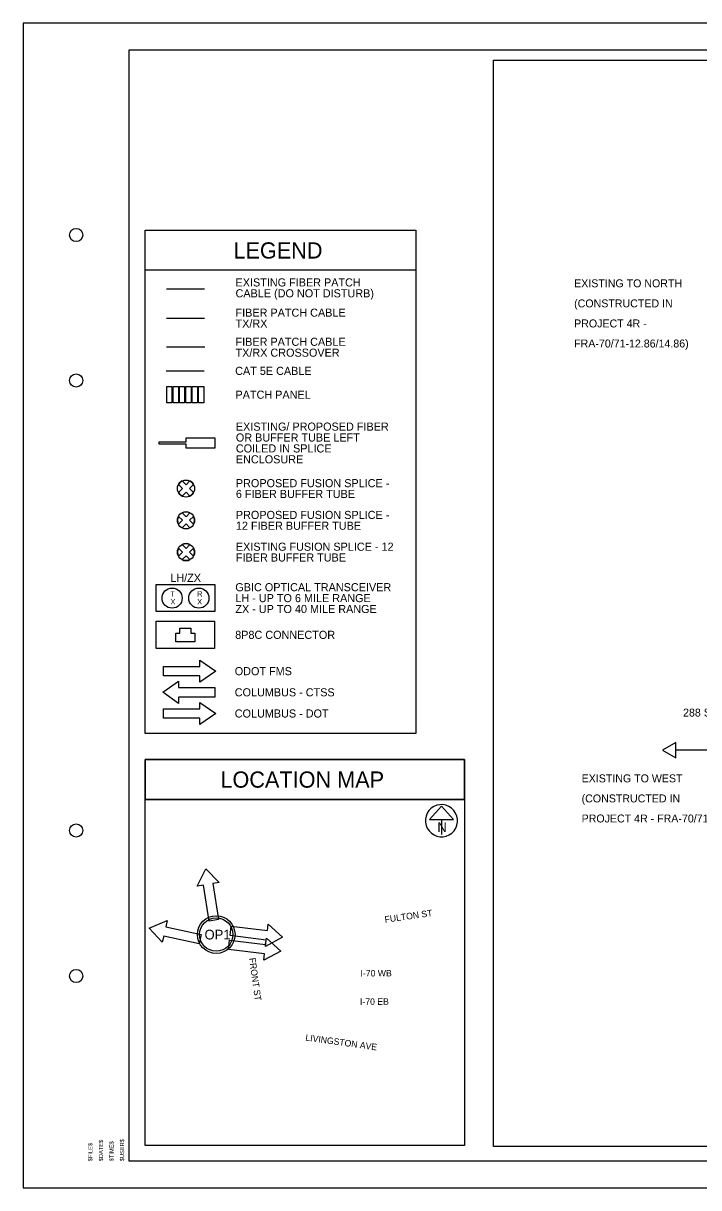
# Model space of a CAD drawing. Extents: x 1805893 to 1833564, y 708898 to 716199.
# Drawn here: x 1831322.5 to 1831577.6, y 715759.4 to 716199.4 of the extents above; entities that cross this region are included whole.
import ezdxf

# ---------------------------------------------------------------- set-up
doc = ezdxf.new("R2010")
doc.units = 0
for name, color, linetype in [('BR_P_Sub_Hidden', 7, 'Continuous'), ('BR_X_Slab_Object', 7, 'Continuous'), ('SH_Border', 7, 'Continuous'), ('SH_Cut_Line', 7, 'Continuous'), ('SH_Data', 7, 'Continuous'), ('SH_Text', 7, 'Continuous'), ('UT_X_Misc_Cells', 7, 'Continuous')]:
    doc.layers.add(name, color=color, linetype=linetype)

msp = doc.modelspace()

# ---------------------------------------------------------------- linework, layer by layer
at = {"layer": 'BR_P_Sub_Hidden'}
msp.add_lwpolyline([(1831500.15, 716185.43), (1831958.68, 716185.43), (1831958.68, 715774.93), (1831500.15, 715774.93)], close=True, dxfattribs=at)
at = {"layer": 'SH_Border'}
msp.add_lwpolyline([(1831362.49, 716189.4), (1831992.49, 716189.4), (1831992.49, 715769.4), (1831362.49, 715769.4)], close=True, dxfattribs=at)
for centre in [(1831342.49, 716119.4), (1831342.49, 716064.4), (1831342.49, 715894.4), (1831342.49, 715839.4)]:
    msp.add_circle(centre, 2.5, dxfattribs=at)
at = {"layer": 'SH_Cut_Line'}
msp.add_lwpolyline([(1831322.49, 715759.4), (1832002.49, 715759.4), (1832002.49, 716199.4), (1831322.49, 716199.4)], close=True, dxfattribs=at)
at = {"layer": 'SH_Data'}
for p, q in [((1831376.65, 716099), (1831390.99, 716099)), ((1831376.65, 716088), (1831390.99, 716088)), ((1831383.96, 716024.96), (1831382.46, 716026.45)), ((1831383.96, 716024.96), (1831382.46, 716026.45)), ((1831383.96, 716024.96), (1831385.45, 716026.45)), ((1831385.45, 716026.45), (1831383.96, 716024.96)), ((1831382.6, 716023.6), (1831381.11, 716025.09)), ((1831381.11, 716025.09), (1831382.6, 716023.6)), ((1831381.11, 716022.11), (1831382.6, 716023.6)), ((1831382.6, 716023.6), (1831381.11, 716022.11)), ((1831382.46, 716020.75), (1831383.96, 716022.25)), ((1831382.46, 716020.75), (1831383.96, 716022.25)), ((1831385.45, 716020.75), (1831383.96, 716022.25)), ((1831383.96, 716022.25), (1831385.45, 716020.75)), ((1831385.31, 716023.6), (1831386.8, 716025.09)), ((1831385.31, 716023.6), (1831386.8, 716025.09)), ((1831386.8, 716022.11), (1831385.31, 716023.6)), ((1831386.8, 716022.11), (1831385.31, 716023.6)), ((1831382.6, 716011.59), (1831381.11, 716013.08)), ((1831382.6, 716011.59), (1831381.11, 716013.08)), ((1831383.96, 716012.95), (1831382.46, 716014.44)), ((1831382.46, 716014.44), (1831383.96, 716012.95)), ((1831383.96, 716012.95), (1831385.45, 716014.44)), ((1831383.96, 716012.95), (1831385.45, 716014.44)), ((1831385.31, 716011.59), (1831386.8, 716013.08)), ((1831386.8, 716013.08), (1831385.31, 716011.59)), ((1831381.11, 716010.1), (1831382.6, 716011.59)), ((1831381.11, 716010.1), (1831382.6, 716011.59)), ((1831382.46, 716008.74), (1831383.96, 716010.24)), ((1831383.96, 716010.24), (1831382.46, 716008.74)), ((1831385.45, 716008.74), (1831383.96, 716010.24)), ((1831385.45, 716008.74), (1831383.96, 716010.24)), ((1831386.8, 716010.1), (1831385.31, 716011.59)), ((1831385.31, 716011.59), (1831386.8, 716010.1)), ((1831382.6, 715999.59), (1831381.11, 716001.08)), ((1831382.6, 715999.59), (1831381.11, 716001.08)), ((1831381.11, 715998.1), (1831382.6, 715999.59)), ((1831381.11, 715998.1), (1831382.6, 715999.59)), ((1831383.96, 716000.95), (1831382.46, 716002.44)), ((1831382.46, 716002.44), (1831383.96, 716000.95)), ((1831383.96, 716000.95), (1831385.45, 716002.44)), ((1831383.96, 716000.95), (1831385.45, 716002.44)), ((1831385.31, 715999.59), (1831386.8, 716001.08)), ((1831386.8, 716001.08), (1831385.31, 715999.59)), ((1831386.8, 715998.1), (1831385.31, 715999.59)), ((1831385.31, 715999.59), (1831386.8, 715998.1)), ((1831382.46, 715996.74), (1831383.96, 715998.23)), ((1831383.96, 715998.23), (1831382.46, 715996.74)), ((1831385.45, 715996.74), (1831383.96, 715998.23)), ((1831385.45, 715996.74), (1831383.96, 715998.23)), ((1831375.5, 715956.4), (1831389.23, 715956.4)), ((1831375.5, 715952.8), (1831375.5, 715956.4)), ((1831389.23, 715956.4), (1831389.23, 715958.8)), ((1831389.23, 715952.8), (1831375.5, 715952.8)), ((1831381.16, 715950.8), (1831381.16, 715948.4)), ((1831389.23, 715950.4), (1831389.23, 715952.8)), ((1831381.16, 715948.4), (1831394.9, 715948.4)), ((1831394.9, 715948.4), (1831394.9, 715944.8)), ((1831394.9, 715944.8), (1831381.16, 715944.8)), ((1831381.16, 715944.8), (1831381.16, 715942.4)), ((1831389.23, 715940.4), (1831389.23, 715942.8)), ((1831375.5, 715940.4), (1831389.23, 715940.4)), ((1831375.5, 715936.8), (1831375.5, 715940.4)), ((1831389.23, 715936.8), (1831375.5, 715936.8)), ((1831389.23, 715934.4), (1831389.23, 715936.8)), ((1831568.97, 715927.63), (1831563.95, 715924.73)), ((1831563.95, 715924.73), (1831568.97, 715921.83)), ((1831568.97, 715921.83), (1831568.97, 715927.63)), ((1831611.7, 715924.73), (1831568.97, 715924.73))]:
    msp.add_line(p, q, dxfattribs=at)
for points in [[(1831368.49, 716121.24), (1831470.72, 716121.24), (1831470.72, 716106.12), (1831368.49, 716106.12)], [(1831470.72, 716121.24), (1831470.72, 715931.07), (1831368.49, 715931.07), (1831368.49, 716121.24)], [(1831378.66, 716062.19), (1831378.66, 716055.94), (1831376.7, 716055.94), (1831376.7, 716062.19)], [(1831381.06, 716062.19), (1831381.06, 716055.94), (1831379.1, 716055.94), (1831379.1, 716062.19)], [(1831383.45, 716062.19), (1831383.45, 716055.94), (1831381.49, 716055.94), (1831381.49, 716062.19)], [(1831385.85, 716062.19), (1831385.85, 716055.94), (1831383.89, 716055.94), (1831383.89, 716062.19)], [(1831388.24, 716062.19), (1831388.24, 716055.94), (1831386.28, 716055.94), (1831386.28, 716062.19)], [(1831390.64, 716062.19), (1831390.64, 716055.94), (1831388.68, 716055.94), (1831388.68, 716062.19)], [(1831372.7, 715987.33), (1831394.8, 715987.33), (1831394.8, 715977.08), (1831372.7, 715977.08)], [(1831372.65, 715973.45), (1831394.74, 715973.45), (1831394.74, 715963.2), (1831372.65, 715963.2)], [(1831489.13, 715906.07), (1831368.49, 715906.07), (1831368.49, 715921.19), (1831489.13, 715921.19)], [(1831489.13, 715921.19), (1831368.49, 715921.19), (1831368.49, 715906.07), (1831489.13, 715906.07)], [(1831489.13, 715906.07), (1831368.49, 715906.07), (1831368.49, 715921.19), (1831489.13, 715921.19)], [(1831489.13, 715906.07), (1831489.13, 715775.4), (1831368.49, 715775.4), (1831368.49, 715906.07)], [(1831489.13, 715906.07), (1831489.13, 715775.4), (1831368.49, 715775.4), (1831368.49, 715906.07)]]:
    msp.add_lwpolyline(points, close=True, dxfattribs=at)
for points in [[(1831391.03, 716077), (1831376.65, 716077), (1831376.65, 716077), (1831376.65, 716077)], [(1831376.52, 716068.06), (1831390.86, 716068.09), (1831390.86, 716068.09)], [(1831373.66, 716041.13), (1831373.66, 716040.82), (1831373.66, 716040.51), (1831383.94, 716040.51), (1831383.94, 716038.98), (1831394.99, 716038.98), (1831394.99, 716042.66), (1831383.94, 716042.66), (1831383.94, 716041.13), (1831373.66, 716041.13)], [(1831394.99, 716038.98), (1831394.99, 716042.66), (1831383.94, 716042.66), (1831383.94, 716041.13), (1831373.66, 716041.13), (1831373.66, 716040.82), (1831373.66, 716040.51), (1831383.94, 716040.51), (1831383.94, 716038.98), (1831394.99, 716038.98)], [(1831385.82, 715968.93), (1831387.33, 715968.93), (1831387.33, 715965.7), (1831380.06, 715965.7), (1831380.06, 715968.93), (1831381.57, 715968.93)], [(1831381.57, 715968.93), (1831381.57, 715970.84), (1831385.82, 715970.84), (1831385.82, 715968.93)], [(1831389.23, 715958.8), (1831395.23, 715954.6), (1831389.23, 715950.4)], [(1831381.16, 715942.4), (1831375.16, 715946.6), (1831381.16, 715950.8)], [(1831389.23, 715942.8), (1831395.23, 715938.6), (1831389.23, 715934.4)]]:
    msp.add_lwpolyline(points, dxfattribs=at)
for centre, radius in [((1831383.96, 716023.6), 3.22), ((1831383.96, 716011.59), 3.22), ((1831383.96, 715999.59), 3.22), ((1831378.7, 715982.2), 3.81), ((1831388.8, 715982.2), 3.81)]:
    msp.add_circle(centre, radius, dxfattribs=at)
for centre, start, end in [((1831383.96, 716023.6), 117.647, 152.353), ((1831383.96, 716023.6), 27.647, 62.353), ((1831383.96, 716023.6), 207.647, 242.353), ((1831383.96, 716023.6), 297.647, 332.353), ((1831383.96, 716011.59), 152.353, 207.647), ((1831383.96, 716011.59), 62.353, 117.647), ((1831383.96, 716011.59), 332.353, 27.647), ((1831383.96, 716011.59), 242.353, 297.647), ((1831383.96, 715999.59), 152.353, 207.647), ((1831383.96, 715999.59), 62.353, 117.647), ((1831383.96, 715999.59), 332.353, 27.647), ((1831383.96, 715999.59), 242.353, 297.647)]:
    msp.add_arc(centre, 3.22, start, end, dxfattribs=at)
at = {"layer": 'SH_Text'}
for p, q in [((1831480.46, 715903.56), (1831475.95, 715898.57)), ((1831484.96, 715898.57), (1831480.46, 715903.56)), ((1831475.95, 715898.57), (1831484.96, 715898.57)), ((1831480.46, 715898.57), (1831480.46, 715892.9)), ((1831390.56, 715873.76), (1831388.19, 715873.39)), ((1831392.66, 715860.18), (1831390.56, 715873.76)), ((1831396.49, 715874.68), (1831394.12, 715874.31)), ((1831394.12, 715874.31), (1831396.22, 715860.73)), ((1831376.79, 715860.34), (1831376.28, 715858)), ((1831396.22, 715860.73), (1831392.66, 715860.18)), ((1831400.62, 715854.65), (1831401.06, 715858.22)), ((1831401.06, 715858.22), (1831414.69, 715856.56)), ((1831414.69, 715856.56), (1831414.98, 715858.94)), ((1831375.52, 715854.48), (1831375.01, 715852.13)), ((1831388.95, 715851.58), (1831375.52, 715854.48)), ((1831376.28, 715858), (1831389.71, 715855.1)), ((1831389.71, 715855.1), (1831388.95, 715851.58)), ((1831414.26, 715852.99), (1831400.62, 715854.65)), ((1831414.05, 715851.31), (1831414.34, 715853.69)), ((1831399.98, 715849.39), (1831400.42, 715852.97)), ((1831413.62, 715847.73), (1831399.98, 715849.39)), ((1831400.42, 715852.97), (1831414.05, 715851.31)), ((1831413.97, 715850.61), (1831414.26, 715852.99)), ((1831413.33, 715845.35), (1831413.62, 715847.73))]:
    msp.add_line(p, q, dxfattribs=at)
for points in [[(1831388.19, 715873.39), (1831391.42, 715879.96), (1831396.49, 715874.68)], [(1831375.01, 715852.13), (1831370.03, 715857.5), (1831376.79, 715860.34)], [(1831414.98, 715858.94), (1831420.43, 715854.05), (1831413.97, 715850.61)], [(1831414.34, 715853.69), (1831419.79, 715848.79), (1831413.33, 715845.35)]]:
    msp.add_lwpolyline(points, dxfattribs=at)
for radius in [7.11, 6.31]:
    msp.add_circle((1831395.37, 715855.05), radius, dxfattribs=at)
msp.add_arc((1831480.46, 715898.09), 6.08, 129.7798, 129.7633, dxfattribs=at)

# ---------------------------------------------------------------- texts
at = {"layer": 'BR_X_Slab_Object'}
for s, p in [('T', (1831378.09, 715982.8)), ('X', (1831378.1, 715979.8)), ('X', (1831388.19, 715979.8)), ('R', (1831388.19, 715982.8))]:
    msp.add_text(s, height=2, rotation=0.0475, dxfattribs=at).set_placement(p)
at = {"layer": 'SH_Data'}
for s, height, p in [('LEGEND', 6.119, (1831401.87, 716110.51)), ('EXISTING FIBER PATCH ', 3.0596, (1831402.67, 716099.96)), ('EXISTING TO NORTH', 3, (1831530.58, 716099.64)), ('CABLE (DO NOT DISTURB)', 3.0596, (1831402.67, 716095.84)), ('FIBER PATCH CABLE', 3.0596, (1831402.67, 716088.53)), ('(CONSTRUCTED IN ', 3, (1831530.58, 716092.06)), ('TX/RX', 3.06, (1831402.67, 716084.41)), ('PROJECT 4R - ', 3, (1831530.58, 716084.48)), ('FIBER PATCH CABLE', 3.0596, (1831402.67, 716077.53)), ('FRA-70/71-12.86/14.86)', 3, (1831530.58, 716076.9)), ('TX/RX CROSSOVER', 3.0596, (1831402.67, 716073.41)), ('CAT 5E CABLE', 3.0596, (1831402.53, 716066.53)), ('PATCH PANEL', 3.0596, (1831402.65, 716057.53)), ('EXISTING/ PROPOSED FIBER ', 3.0596, (1831402.79, 716045.47)), ('OR BUFFER TUBE LEFT ', 3.0596, (1831402.79, 716041.35)), ('COILED IN SPLICE ', 3.0596, (1831402.79, 716037.23)), ('ENCLOSURE', 3.06, (1831402.79, 716033.11)), ('PROPOSED FUSION SPLICE - ', 3.0596, (1831402.8, 716024.11)), ('6 FIBER BUFFER TUBE', 3.0596, (1831402.8, 716020.03)), ('PROPOSED FUSION SPLICE - ', 3.0596, (1831402.8, 716012.1)), ('12 FIBER BUFFER TUBE', 3.0596, (1831402.8, 716008.02)), ('EXISTING FUSION SPLICE - 12 ', 3.0596, (1831402.8, 716000.09)), ('FIBER BUFFER TUBE', 3.0596, (1831402.8, 715996.02)), ('LH/ZX', 3.06, (1831378.02, 715988.33)), ('GBIC OPTICAL TRANSCEIVER', 3.0596, (1831402.6, 715984.79)), ('LH - UP TO 6 MILE RANGE', 3.0596, (1831402.6, 715980.67)), ('ZX - UP TO 40 MILE RANGE', 3.0596, (1831402.6, 715976.55)), ('8P8C CONNECTOR', 3.0596, (1831402.54, 715966.79)), ('ODOT FMS', 3.06, (1831402.37, 715953.07)), ('COLUMBUS - CTSS', 3.0596, (1831402.37, 715945.07)), ('COLUMBUS - DOT', 3.0596, (1831402.37, 715937.07)), ('288 STRAND FOC', 3, (1831571.73, 715937.44)), ('LOCATION MAP', 6.1191, (1831396.95, 715910.57)), ('EXISTING TO WEST', 3, (1831533.41, 715912.58)), ('(CONSTRUCTED IN ', 3, (1831533.41, 715905)), ('PROJECT 4R - FRA-70/71-12.86/14.86)', 3, (1831533.41, 715897.42))]:
    msp.add_text(s, height=height, dxfattribs=at).set_placement(p)
at = {"layer": 'SH_Text'}
for s, height, rotation, p in [('N', 3.66, 360, (1831478.93, 715893.82)), ('FULTON ST', 2.448, 8.061, (1831459.17, 715859.52)), ('FRONT ST', 2.448, 278.061, (1831407.75, 715846.1)), ('I-70 WB', 2.448, 0.3445, (1831449.87, 715839.2)), ('I-70 EB', 2.448, 0.3445, (1831449.68, 715828.46)), ('LIVINGSTON AVE', 2.4477, 352.086, (1831428.95, 715815.02))]:
    msp.add_text(s, height=height, rotation=rotation, dxfattribs=at).set_placement(p)
msp.add_text('OP1', height=3.671, dxfattribs=at).set_placement((1831390.96, 715853.21))
at = {"layer": 'UT_X_Misc_Cells'}
for s, p in [('$FILE$', (1831348.59, 715769.4)), ('$DATE$', (1831352.59, 715769.4)), ('$TIME$', (1831356.59, 715769.4)), ('$USER$', (1831360.59, 715769.4))]:
    msp.add_text(s, height=1.56, rotation=90, dxfattribs=at).set_placement(p)

doc.saveas('drawing.dxf')
